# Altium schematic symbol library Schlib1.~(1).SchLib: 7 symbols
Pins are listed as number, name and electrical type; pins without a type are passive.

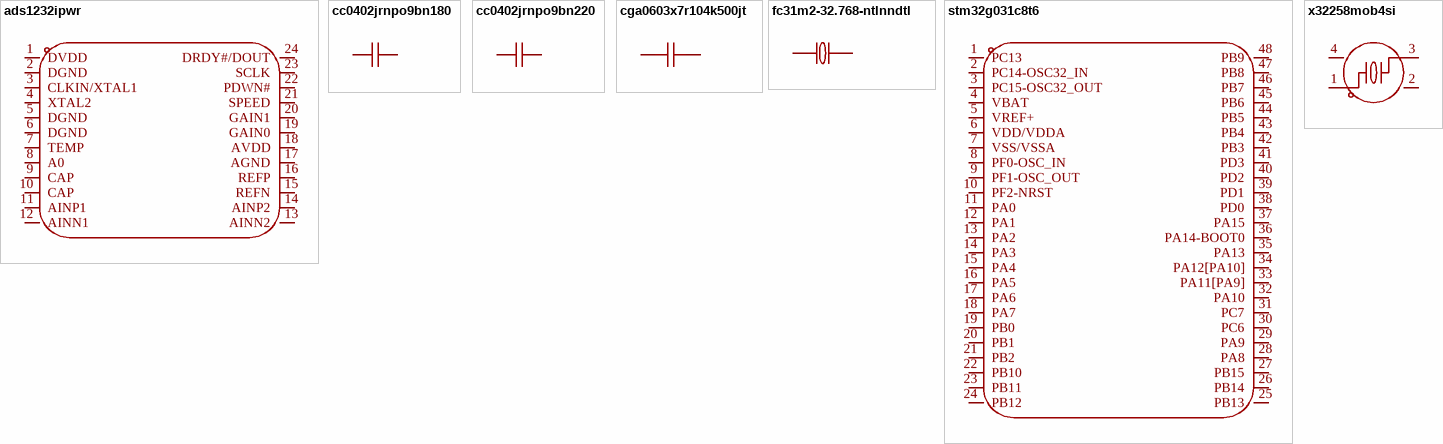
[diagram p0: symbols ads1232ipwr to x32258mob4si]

## ads1232ipwr
designator U??  (value not drawn)
分辨率(位):24;采样率:10Hz;工作电压:2.7V~5.3V;接口类型:SPI;; Manufacturer: TI(德州仪器); AddInBom: yes; ModelId: 57e278220af748a2882c4abba4094eb9; ModelName: TSSOP-24_L7.8-W4.4-H1.0-LS6.4-P0.65; ModelTransform: 252.188,307.086,0,90,0,0,0,0,0; Resolution (Bits): 24; Sampling Rate: 10Hz; number of channels: 2; Interface: SPI; differential input: 是; Clock/Oscillator: 内置；外置; Clock Frequency: 4.9152MHz；200kHz~8MHz; Voltage Reference: 外置; Programmable Gain: 支持; Temperature Sensors: 内置; ADC architecture: Sigma-Delta; Data rate: 80Hz；10Hz; Quiescent Current (Iq): 1.3uA; Full-Scale Range(FSR): 39mV；1.25V；19.5mV；2.5V
footprint TSSOP-24_L7.8-W4.4-P0.65-LS6.4-BL
footprint Model Name (Footprint not found)
pins: 1 DVDD, 2 DGND, 3 CLKIN/XTAL1, 4 XTAL2, 5 DGND, 6 DGND, 7 TEMP, 8 A0, 9 CAP, 10 CAP, 11 AINP1, 12 AINN1, 13 AINN2, 14 AINP2, 15 REFN, 16 REFP, 17 AGND, 18 AVDD, 19 GAIN0, 20 GAIN1, 21 SPEED, 22 PDWN#, 23 SCLK, 24 DRDY#/DOUT

## cc0402jrnpo9bn180
designator C??  (value not drawn)
容值:18pF;精度:±5%;额定电压:50V;温度系数:NP0;; Manufacturer: YAGEO(国巨); AddInBom: yes; ModelId: 36a51122f27c49738f86b3bfa98863e0; ModelName: C0402_L1.0-W0.5-H0.5; ModelTransform: 39.37,19.685,0,0,0,0,0,0,0; Value: 18pF; Tolerance: ±5%; Voltage Rating: 50V; Temperature Coefficient: NP0
footprint C0402
pins: 1, 2

## cc0402jrnpo9bn220
designator C??  (value not drawn)
容值:22pF;精度:±5%;额定电压:50V;温度系数:NP0;; Manufacturer: YAGEO(国巨); AddInBom: yes; ModelId: 36a51122f27c49738f86b3bfa98863e0; ModelName: C0402_L1.0-W0.5-H0.5; ModelTransform: 39.37,19.685,0,0,0,0,0,0,0; Value: 22pF; Tolerance: ±5%; Voltage Rating: 50V; Temperature Coefficient: NP0
footprint C0402
pins: 1, 2

## cga0603x7r104k500jt
designator C??  (value not drawn)
容值:100nF;精度:±10%;额定电压:50V;温度系数:X7R;; Manufacturer: HRE(芯声); AddInBom: yes; ModelId: ac125912035d415993ca9572d50418b1; ModelName: C0603_L1.6-W0.8-H0.8; ModelTransform: 62.992,31.496,0,0,0,0,0,0,0; Value: 100nF; Tolerance: ±10%; Voltage Rating: 50V; Temperature Coefficient: X7R
footprint C0603
footprint Model Name (Footprint not found)
pins: 1, 2

## fc31m2-32.768-ntlnndtl
designator U??  (value not drawn)
晶振类型:贴片晶振;频率:32.768kHz;常温频差:±10ppm;负载电容:12.5pF;频率稳定度:±10ppm;; Manufacturer: HCI(杭晶); AddInBom: yes; ModelId: 762d7afc596f4558a373612390f4386d; ModelName: CRYSTAL-SMD_L3.2-W1.5-1; ModelTransform: 125.984,59.055,0,0,0,0,0,0,0; Normal temperature Frequency Tolerance: ±10ppm; Load Capacitance: 12.5pF; Equivalent Series Resistance(ESR): 70kΩ
footprint CRYSTAL-SMD_L3.2-W1.5
pins: 1, 2

## stm32g031c8t6
designator U??  (value not drawn)
CPU内核:ARM Cortex-M0+;CPU最大主频:64MHz;CPU位数:32 Bit;; Manufacturer: ST(意法半导体); AddInBom: yes; ModelId: 093be70396ff421eb2cdb946d5311efc; ModelName: LQFP-48_L7.0-W7.0-H1.4-LS9.0-P0.50; ModelTransform: 354.331,354.331,0,0,0,0,0,0,0; CPU Maximum Speed: 64MHz; Core Size: 32 Bit; Program Storage Size: 64KB; Program Memory Type: FLASH; RAM Size: 8KB; Number of I/O: 44; ADC (Bit): 12bit; Oscillator Type: 内置+外置; Voltage - Supply: 1.7V~3.6V
footprint LQFP-48_L7.0-W7.0-P0.50-LS9.0-BL
pins: 1 PC13, 2 PC14-OSC32_IN, 3 PC15-OSC32_OUT, 4 VBAT, 5 VREF+, 6 VDD/VDDA, 7 VSS/VSSA, 8 PF0-OSC_IN, 9 PF1-OSC_OUT, 10 PF2-NRST, 11 PA0, 12 PA1, 13 PA2, 14 PA3, 15 PA4, 16 PA5, 17 PA6, 18 PA7, 19 PB0, 20 PB1, 21 PB2, 22 PB10, 23 PB11, 24 PB12, 25 PB13, 26 PB14, 27 PB15, 28 PA8, 29 PA9, 30 PC6, 31 PC7, 32 PA10, 33 PA11[PA9], 34 PA12[PA10], 35 PA13, 36 PA14-BOOT0, 37 PA15, 38 PD0, 39 PD1, 40 PD2, 41 PD3, 42 PB3, 43 PB4, 44 PB5, 45 PB6, 46 PB7, 47 PB8, 48 PB9

## x32258mob4si
designator X??  (value not drawn)
晶振类型:贴片晶振;频率:8MHz;常温频差:±10ppm;负载电容:12pF;频率稳定度:±20ppm;; Manufacturer: YXC(扬兴晶振); AddInBom: yes; ModelId: ff2dfd5650294453a14147960efe1838; ModelName: CRYSTAL-SMD_4P-L3.2-W2.5-BL; ModelTransform: 125.984,98.425,0,0,0,0,0,0,0; Value: 8MHz; Normal temperature Frequency Tolerance: ±10ppm; Load Capacitance: 12pF; Frequency Stability: ±20ppm; Equivalent Series Resistance(ESR): 180Ω
footprint CRYSTAL-SMD_4P-L3.2-W2.5-BL
pins: 1, 2 GND, 3, 4 GND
